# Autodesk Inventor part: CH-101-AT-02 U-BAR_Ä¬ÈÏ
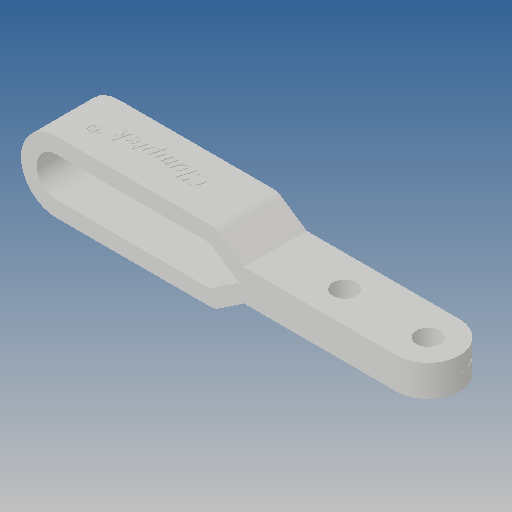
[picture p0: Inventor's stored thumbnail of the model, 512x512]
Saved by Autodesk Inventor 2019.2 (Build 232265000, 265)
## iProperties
Created: 2010-06
Part Number: CH-101-AT-02 U-BAR_Ä¬ÈÏ
Material: Ogólny
Document SubType Name: Modeling
Designer: CADENGINEERING4
Density: 1 g/cm^3
Appearance: Domyślna
Author: CADENGINEERING4
Revision Number: ÈÎºÎ
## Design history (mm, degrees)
feature "NONE"
feature "NONE:1"
node "Bryła1"
node "Bryła2"
